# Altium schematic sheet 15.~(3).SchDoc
size 401 x 287 mm
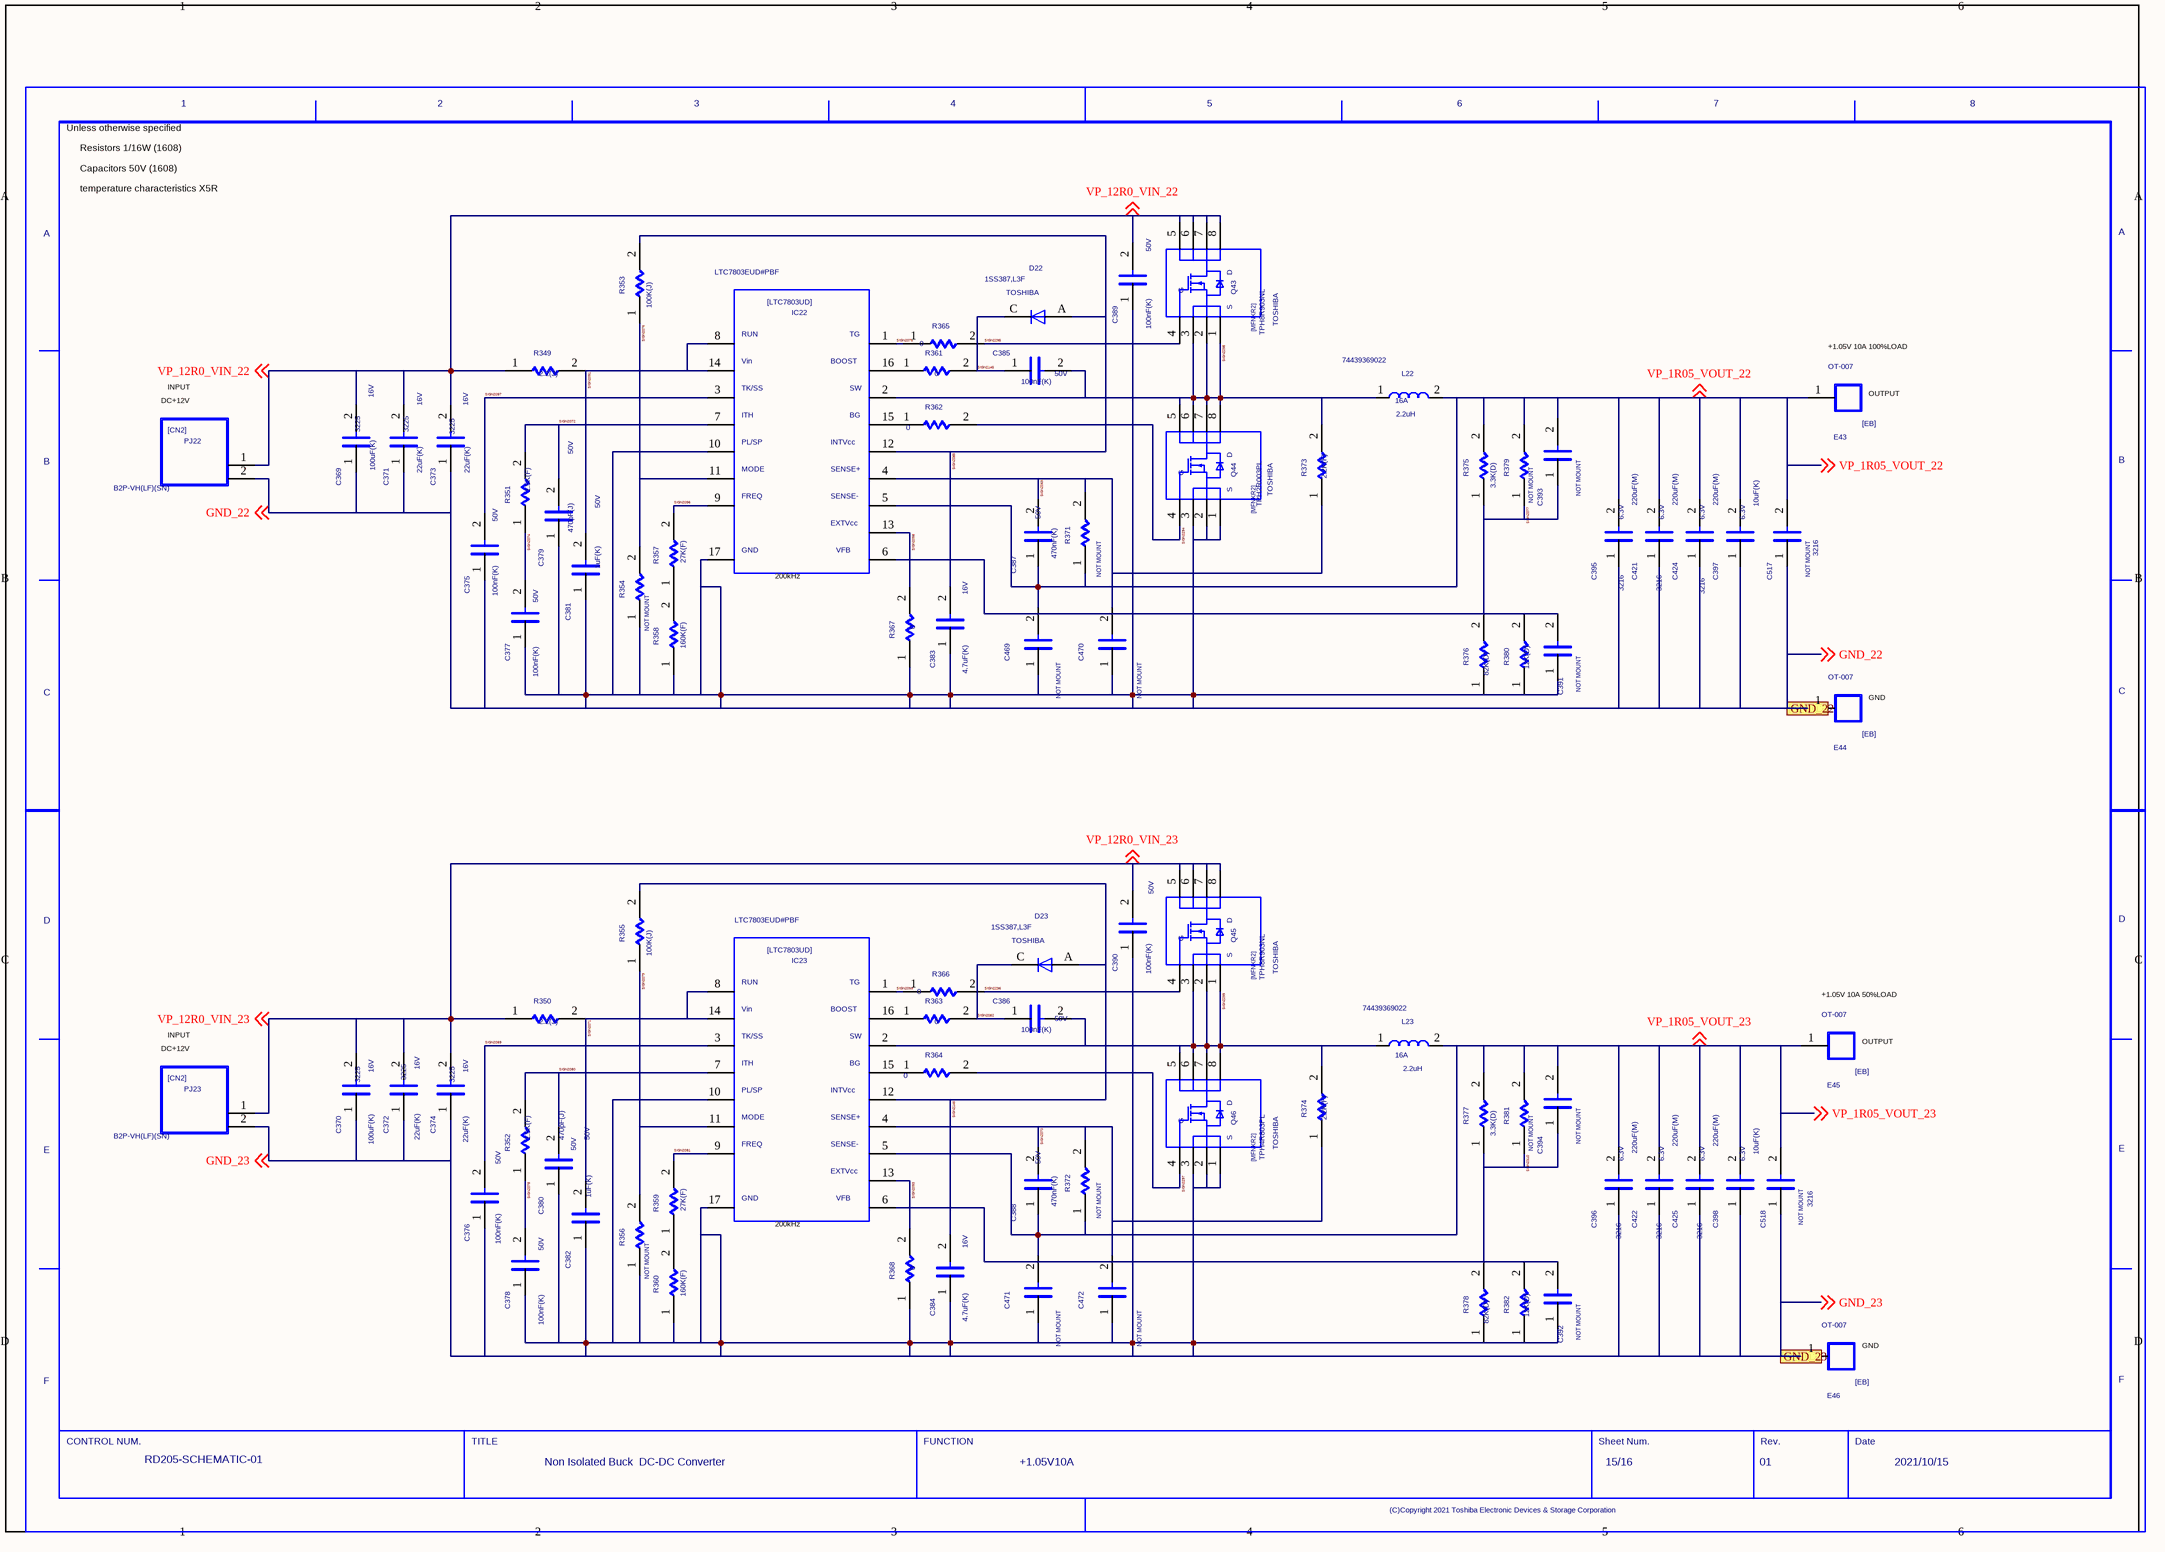
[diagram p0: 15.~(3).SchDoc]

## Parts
C369  SIZECODESMD: 3225  VAL2: 16V  VAL1: 100uF(K)  (hidden comment: C)
C370  SIZECODESMD: 3225  VAL2: 16V  VAL1: 100uF(K)  (hidden comment: C)
C371  SIZECODESMD: 3225  VAL2: 16V  VAL1: 22uF(K)  (hidden comment: C)
C372  SIZECODESMD: 3225  VAL2: 16V  VAL1: 22uF(K)  (hidden comment: C)
C373  SIZECODESMD: 3225  VAL2: 16V  VAL1: 22uF(K)  (hidden comment: C)
C374  SIZECODESMD: 3225  VAL2: 16V  VAL1: 22uF(K)  (hidden comment: C)
C375  VAL2: 50V  VAL1: 100nF(K)  (hidden comment: C)
C376  VAL2: 50V  VAL1: 100nF(K)  (hidden comment: C)
C377  VAL2: 50V  VAL1: 100nF(K)  (hidden comment: C)
C378  VAL2: 50V  VAL1: 100nF(K)  (hidden comment: C)
C379  VAL2: 50V  VAL1: 470pF(J)  (hidden comment: C)
C380  VAL2: 50V  VAL1: 470pF(J)  (hidden comment: C)
C381  VAL2: 50V  VAL1: 1uF(K)  (hidden comment: C)
C382  VAL2: 50V  VAL1: 1uF(K)  (hidden comment: C)
C383  VAL2: 16V  VAL1: 4.7uF(K)  (hidden comment: C)
C384  VAL2: 16V  VAL1: 4.7uF(K)  (hidden comment: C)
C385  VAL2: 50V  VAL1: 100nF(K)  (hidden comment: C)
C386  VAL2: 50V  VAL1: 100nF(K)  (hidden comment: C)
C387  VAL2: 50V  VAL1: 470nF(K)  (hidden comment: C)
C388  VAL2: 50V  VAL1: 470nF(K)  (hidden comment: C)
C389  VAL2: 50V  VAL1: 100nF(K)  (hidden comment: C)
C390  VAL2: 50V  VAL1: 100nF(K)  (hidden comment: C)
C391  NOTMOUNT: NOT MOUNT  (hidden comment: C)
C392  NOTMOUNT: NOT MOUNT  (hidden comment: C)
C393  NOTMOUNT: NOT MOUNT  (hidden comment: C)
C394  NOTMOUNT: NOT MOUNT  (hidden comment: C)
C395  SIZECODESMD: 3216  VAL2: 6.3V  VAL1: 220uF(M)  (hidden comment: C)
C396  SIZECODESMD: 3216  VAL2: 6.3V  VAL1: 220uF(M)  (hidden comment: C)
C397  VAL2: 6.3V  VAL1: 10uF(K)  (hidden comment: C)
C398  VAL2: 6.3V  VAL1: 10uF(K)  (hidden comment: C)
C421  SIZECODESMD: 3216  VAL2: 6.3V  VAL1: 220uF(M)  (hidden comment: C)
C422  SIZECODESMD: 3216  VAL2: 6.3V  VAL1: 220uF(M)  (hidden comment: C)
C424  SIZECODESMD: 3216  VAL2: 6.3V  VAL1: 220uF(M)  (hidden comment: C)
C425  SIZECODESMD: 3216  VAL2: 6.3V  VAL1: 220uF(M)  (hidden comment: C)
C469  NOTMOUNT: NOT MOUNT  (hidden comment: C)
C470  NOTMOUNT: NOT MOUNT  (hidden comment: C)
C471  NOTMOUNT: NOT MOUNT  (hidden comment: C)
C472  NOTMOUNT: NOT MOUNT  (hidden comment: C)
C517  NOTMOUNT: NOT MOUNT  SIZECODESMD: 3216  (hidden comment: C)
C518  NOTMOUNT: NOT MOUNT  SIZECODESMD: 3216  (hidden comment: C)
D22  USERCOMPTEXT3: TOSHIBA  VAL3: 1SS387,L3F  (hidden comment: D)
D23  USERCOMPTEXT3: TOSHIBA  VAL3: 1SS387,L3F  (hidden comment: D)
E43  VAL3: OT-007  (hidden comment: EB)
E44  VAL3: OT-007  (hidden comment: EB)
E45  VAL3: OT-007  (hidden comment: EB)
E46  VAL3: OT-007  (hidden comment: EB)
IC22  VAL3: LTC7803EUD#PBF  (hidden comment: LTC7803UD)
IC23  VAL3: LTC7803EUD#PBF  (hidden comment: LTC7803UD)
L22  VAL3: 74439369022  VAL2: 16A  VAL1: 2.2uH  (hidden comment: L)
L23  VAL3: 74439369022  VAL2: 16A  VAL1: 2.2uH  (hidden comment: L)
PJ22  VAL3: B2P-VH(LF)(SN)  (hidden comment: CN2)
PJ23  VAL3: B2P-VH(LF)(SN)  (hidden comment: CN2)
Q43  USERCOMPTEXT3: TOSHIBA  VAL3: TPH8R903NL  (hidden comment: MFNKR2)
Q44  USERCOMPTEXT3: TOSHIBA  VAL3: TPH2R003PL  (hidden comment: MFNKR2)
Q45  USERCOMPTEXT3: TOSHIBA  VAL3: TPH8R903NL  (hidden comment: MFNKR2)
Q46  USERCOMPTEXT3: TOSHIBA  VAL3: TPH4R803PL  (hidden comment: MFNKR2)
R349  VAL1: 2.2(J)  (hidden comment: R)
R350  VAL1: 2.2(J)  (hidden comment: R)
R351  VAL1: 1.5K(F)  (hidden comment: R)
R352  VAL1: 1.5K(F)  (hidden comment: R)
R353  VAL1: 100K(J)  (hidden comment: R)
R354  NOTMOUNT: NOT MOUNT  (hidden comment: R)
R355  VAL1: 100K(J)  (hidden comment: R)
R356  NOTMOUNT: NOT MOUNT  (hidden comment: R)
R357  VAL1: 27K(F)  (hidden comment: R)
R358  VAL1: 160K(F)  (hidden comment: R)
R359  VAL1: 27K(F)  (hidden comment: R)
R360  VAL1: 160K(F)  (hidden comment: R)
R361  VAL1: 0  (hidden comment: R)
R362  VAL1: 0  (hidden comment: R)
R363  VAL1: 0  (hidden comment: R)
R364  VAL1: 0  (hidden comment: R)
R365  VAL1: 0  (hidden comment: R)
R366  VAL1: 0  (hidden comment: R)
R367  VAL1: 0  (hidden comment: R)
R368  VAL1: 0  (hidden comment: R)
R371  NOTMOUNT: NOT MOUNT  (hidden comment: R)
R372  NOTMOUNT: NOT MOUNT  (hidden comment: R)
R373  VAL1: 2.2K(F)  (hidden comment: R)
R374  VAL1: 2.2K(F)  (hidden comment: R)
R375  VAL1: 3.3K(D)  (hidden comment: R)
R376  VAL1: 82K(D)  (hidden comment: R)
R377  VAL1: 3.3K(D)  (hidden comment: R)
R378  VAL1: 82K(D)  (hidden comment: R)
R379  NOTMOUNT: NOT MOUNT  (hidden comment: R)
R380  VAL1: 12K(D)  (hidden comment: R)
R381  NOTMOUNT: NOT MOUNT  (hidden comment: R)
R382  VAL1: 12K(D)  (hidden comment: R)
U?  DATE: 2021/10/15  SHEETNUMBER: 15/16  TITLE: Non Isolated Buck / DC-DC Converter  REVISION: 01  DRAWINGNUMBER: RD205-SCHEMATIC-01  FUNCTION: +1.05V10A  (hidden comment: WAKU_DEF100)

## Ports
GND_22, GND_23

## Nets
GND_22: C369.1 C371.1 C373.1 C375.1 C377.1 C379.1 C381.1 C383.1 C389.1 C391.1 C395.1 C397.1 C421.1 C424.1 C469.1 C470.1 C517.1 E44.1 IC22.10 IC22.17 PJ22.2 Q44.1 Q44.2 Q44.3 R354.1 R358.1 R367.1 R376.1 R380.1 ; off-sheet GND_22, port GND_22
GND_23: C370.1 C372.1 C374.1 C376.1 C378.1 C380.1 C382.1 C384.1 C390.1 C392.1 C396.1 C398.1 C422.1 C425.1 C471.1 C472.1 C518.1 E46.1 IC23.10 IC23.17 PJ23.2 Q46.1 Q46.2 Q46.3 R356.1 R360.1 R368.1 R378.1 R382.1 ; off-sheet GND_23, port GND_23
SIGN2069: C387.2 C470.2 IC22.4 R371.2 R373.1
SIGN2071: C382.2 IC23.8 IC23.14 R350.2
SIGN2072: C379.2 IC22.7 R351.2
SIGN2073: C388.2 C472.2 IC23.4 R372.2 R374.1
SIGN2074: C377.2 R351.1
SIGN2075: IC22.1 R365.1
SIGN2076: IC22.11 R353.1 R354.2
SIGN2077: C391.2 C393.1 IC22.6 R375.1 R376.2 R379.1 R380.2
SIGN2078: C378.2 R352.1
SIGN2079: IC23.11 R355.1 R356.2
SIGN2080: C380.2 IC23.7 R352.2
SIGN2081: IC23.9 R359.2
SIGN2082: C386.1 D23.C R363.2
SIGN2085: C383.2 D22.A IC22.12 R353.2
SIGN2089: C376.2 IC23.3
SIGN2091: C381.2 IC22.8 IC22.14 R349.2
SIGN2093: IC23.13 R368.2
SIGN2096: IC22.9 R357.2
SIGN2097: C375.2 IC22.3
SIGN2098: IC22.13 R367.2
SIGN2099: IC23.1 R366.1
SIGN2145: C385.1 D22.C R361.2
SIGN2146: C384.2 D23.A IC23.12 R355.2
SIGN2294: Q44.4 R362.2
SIGN2295: Q43.4 R365.2
SIGN2296: Q45.4 R366.2
SIGN2297: Q46.4 R364.2
SIGN2298: C385.2 IC22.2 L22.1 Q43.1 Q43.2 Q43.3 Q44.5 Q44.6 Q44.7 Q44.8 R373.2
SIGN2299: C386.2 IC23.2 L23.1 Q45.1 Q45.2 Q45.3 Q46.5 Q46.6 Q46.7 Q46.8 R374.2
SIGN2310: C392.2 C394.1 IC23.6 R377.1 R378.2 R381.1 R382.2
VP_1R05_VOUT_22: C387.1 C393.2 C395.2 C397.2 C421.2 C424.2 C469.2 C517.2 E43.1 IC22.5 L22.2 R371.1 R375.2 R379.2 ; off-sheet VP_1R05_VOUT_22
VP_1R05_VOUT_23: C388.1 C394.2 C396.2 C398.2 C422.2 C425.2 C471.2 C518.2 E45.1 IC23.5 L23.2 R372.1 R377.2 R381.2 ; off-sheet VP_1R05_VOUT_23
VP_12R0_VIN_22: C369.2 C371.2 C373.2 C389.2 PJ22.1 Q43.5 Q43.6 Q43.7 Q43.8 R349.1 ; off-sheet VP_12R0_VIN_22
VP_12R0_VIN_23: C370.2 C372.2 C374.2 C390.2 PJ23.1 Q45.5 Q45.6 Q45.7 Q45.8 R350.1 ; off-sheet VP_12R0_VIN_23
NetIC22_15: IC22.15 R362.1
NetIC22_16: IC22.16 R361.1
NetIC23_15: IC23.15 R364.1
NetIC23_16: IC23.16 R363.1
NetR357_1: R357.1 R358.2
NetR359_1: R359.1 R360.2

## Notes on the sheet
- Unless otherwise specified
- Resistors 1/16W (1608)
- Capacitors 50V (1608)
- temperature characteristics X5R
- DC+12V
- INPUT
- (near E43) +1.05V 10A 100%LOAD
- (near E43) OUTPUT
- (near IC22) 200kHz
- (near E44) GND
- (near E45) +1.05V 10A 50%LOAD
- (near E45) OUTPUT
- (near IC23) 200kHz
- (near E46) GND

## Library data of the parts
C369 C370 = C: SQ_PART_MODEL: CON_100n; FNPARTSNAMEG: CHIP CERAMIC CAPACITOR (3225); USEINPARTSLIST: YES; OriginalSymbolOrigin: (2540,7620); MFSOLDERINGPROP: .; TEMPCHARACTERI2: B; MFFORMINGDIVP: KC; OUMECLASSIFICATION: セラミックコンデンサ; MFMOUNTSYMBOLP: 90; CDMASTERCADCELG: DC903A; PCODE: P03276001115; FNCLASSCODEG: P03-03; MAXGCOUNT: 1; RATEDVOLTAGE: 250; COMPONENTNAME: G36030160049; OUMEMAKER: KYC 京セラ; MFPACKAGEMETHOP: S; NOMINALCAPACITA: 100n; OUMEMAKERKATAMEI: CF32W5R104K250AT; CAPACITANCETOLE: K
C371-C374 = C: SQ_PART_MODEL: CON_22u; FNPARTSNAMEG: CHIP CERAMIC CAPACITOR (3225); USEINPARTSLIST: YES; OriginalSymbolOrigin: (2540,7620); MFSOLDERINGPROP: .; TEMPCHARACTERI2: B; MFFORMINGDIVP: KC; OUMECLASSIFICATION: セラミックコンデンサ; MFMOUNTSYMBOLP: 80; CDMASTERCADCELG: DC903A; PCODE: P03043035626; FNCLASSCODEG: P03-03; MAXGCOUNT: 1; RATEDVOLTAGE: 6.3; COMPONENTNAME: G36030119054; OUMEMAKER: TYD 太陽誘電; MFPACKAGEMETHOP: S; NOMINALCAPACITA: 22u; OUMEMAKERKATAMEI: JMK325BJ226KM-T; CAPACITANCETOLE: K
C375-C378 C385 C386 C389 C390 = C: SQ_PART_MODEL: CON_100n; FNPARTSNAMEG: CHIP CERAMIC CAPACITOR (1608); USEINPARTSLIST: YES; OriginalSymbolOrigin: (2540,7620); MFSOLDERINGPROP: .; TEMPCHARACTERI2: B; MFFORMINGDIVP: KC; OUMECLASSIFICATION: セラミックコンデンサ; SIZECODESMD: 1608; MFMOUNTSYMBOLP: 80; CDMASTERCADCELG: C8100E; PCODE: P03B000000E4; FNCLASSCODEG: P03-03; MAXGCOUNT: 1; RATEDVOLTAGE: 16; COMPONENTNAME: GDM030000598; OUMEMAKER: MRT 村田製作所; MFPACKAGEMETHOP: S; NOMINALCAPACITA: 100n; OUMEMAKERKATAMEI: GRM188B11C104KA01C; CAPACITANCETOLE: K
C379 C380 = C: SQ_PART_MODEL: CON_470p; FNPARTSNAMEG: CHIP CERAMIC CAPACITOR (1608); USEINPARTSLIST: YES; OriginalSymbolOrigin: (2540,7620); TOLERANCE: J; ASIMVALUE: 470P; CDMASTERCADCELG: C8100E; MFSOLDERINGPROP: .; TEMPCHARACTERI2: CH; MFFORMINGDIVP: KC; OUMECLASSIFICATION: セラミックコンデンサ; SIZECODESMD: 1608; MFMOUNTSYMBOLP: 80; PCODE: P03039329128; FNCLASSCODEG: P03-03; MAXGCOUNT: 1; RATEDVOLTAGE: 50; COMPONENTNAME: G36030011372; OUMEMAKER: KYC 京セラ; MFPACKAGEMETHOP: S; OUMEMAKERKATAMEI: CM105CH471J50AT
C381 C382 = C: SQ_PART_MODEL: CON_1u; FNPARTSNAMEG: CHIP CERAMIC CAPACITOR (1608); USEINPARTSLIST: YES; OriginalSymbolOrigin: (2540,7620); MFSOLDERINGPROP: .; TEMPCHARACTERI2: B; MFFORMINGDIVP: KC; OUMECLASSIFICATION: セラミックコンデンサ; SIZECODESMD: 1608; MFMOUNTSYMBOLP: 80; CDMASTERCADCELG: C8100E; PCODE: P03039ACE122; FNCLASSCODEG: P03-03; MAXGCOUNT: 1; RATEDVOLTAGE: 6.3; COMPONENTNAME: G36030104159; OUMEMAKER: KYC 京セラ; MFPACKAGEMETHOP: S; NOMINALCAPACITA: 1u; OUMEMAKERKATAMEI: CM105B105K06ATN; CAPACITANCETOLE: K
C383 C384 = C: SQ_PART_MODEL: CON_4.7u; FNPARTSNAMEG: CHIP CERAMIC CAPACITOR (1608); USEINPARTSLIST: YES; OriginalSymbolOrigin: (2540,7620); MFSOLDERINGPROP: .; TEMPCHARACTERI2: B; MFFORMINGDIVP: KC; OUMECLASSIFICATION: セラミックコンデンサ; SIZECODESMD: 1608; MFMOUNTSYMBOLP: 80; CDMASTERCADCELG: C8100E; PCODE: P03B000000MS; FNCLASSCODEG: P03-03; MAXGCOUNT: 1; RATEDVOLTAGE: 4; COMPONENTNAME: GDM030000053; OUMEMAKER: KYC 京セラ; MFPACKAGEMETHOP: S; NOMINALCAPACITA: 4.7u; OUMEMAKERKATAMEI: CM105B475M04AT; CAPACITANCETOLE: M
C387 C388 = C: SQ_PART_MODEL: CON_470n; FNPARTSNAMEG: CHIP CERAMIC CAPACITOR (1608); USEINPARTSLIST: YES; OriginalSymbolOrigin: (2540,7620); MFSOLDERINGPROP: .; TEMPCHARACTERI2: B; MFFORMINGDIVP: KC; OUMECLASSIFICATION: セラミックコンデンサ; SIZECODESMD: 1608; MFMOUNTSYMBOLP: 80; CDMASTERCADCELG: C8100E; PCODE: P03039ABG127; FNCLASSCODEG: P03-03; MAXGCOUNT: 1; RATEDVOLTAGE: 10; COMPONENTNAME: GDM030001129; OUMEMAKER: KYC 京セラ; MFPACKAGEMETHOP: S; NOMINALCAPACITA: 470n; OUMEMAKERKATAMEI: CM105B474K10AT; CAPACITANCETOLE: K
C391-C394 = C: SQ_PART_MODEL: CON_100p; FNPARTSNAMEG: CHIP CERAMIC CAPACITOR (1608); USEINPARTSLIST: YES; OriginalSymbolOrigin: (2540,7620); TOLERANCE: J; ASIMVALUE: 100P; MFSOLDERINGPROP: .; TEMPCHARACTERI2: CH; MFFORMINGDIVP: KC; OUMECLASSIFICATION: セラミックコンデンサ; SIZECODESMD: 1608; MFMOUNTSYMBOLP: 80; CDMASTERCADCELG: C8100E; PCODE: P03039177125; FNCLASSCODEG: P03-03; MAXGCOUNT: 1; RATEDVOLTAGE: 50; COMPONENTNAME: G36030011365; OUMEMAKER: KYC 京セラ; MFPACKAGEMETHOP: S; OUMEMAKERKATAMEI: CM105CH101J50AT; VAL2: 50V; VAL1: 100pF(J)
C395 C396 C421 C422 C424 C425 = C: SQ_PART_MODEL: CON_22u; FNPARTSNAMEG: CHIP CERAMIC CAPACITOR (3216); USEINPARTSLIST: YES; OriginalSymbolOrigin: (2540,7620); MFSOLDERINGPROP: .; TEMPCHARACTERI2: B; MFFORMINGDIVP: KC; OUMECLASSIFICATION: セラミックコンデンサ; MFMOUNTSYMBOLP: 80; CDMASTERCADCELG: DC901A; PCODE: P03B0000004V; FNCLASSCODEG: P03-03; MAXGCOUNT: 1; RATEDVOLTAGE: 6.3; COMPONENTNAME: GDM030000020; OUMEMAKER: KYC 京セラ; MFPACKAGEMETHOP: S; NOMINALCAPACITA: 22u; OUMEMAKERKATAMEI: CM316B226M06AT; CAPACITANCETOLE: M
C397 C398 = C: SQ_PART_MODEL: CON_1u; FNPARTSNAMEG: CHIP CERAMIC CAPACITOR (1608); PARTCOMMENT: 代表セル<KC0008> がフットプリントに登録されていません。; USEINPARTSLIST: YES; OriginalSymbolOrigin: (2540,7620); MFSOLDERINGPROP: .; TEMPCHARACTERI2: B; MFFORMINGDIVP: KC; OUMECLASSIFICATION: セラミックコンデンサ; SIZECODESMD: 1608; MFMOUNTSYMBOLP: 80; CDMASTERCADCELG: KC0008; PCODE: P03B000000ZQ; FNCLASSCODEG: P03-03; MAXGCOUNT: 1; RATEDVOLTAGE: 6.3; COMPONENTNAME: GDM030000202; OUMEMAKER: MRT 村田製作所; MFPACKAGEMETHOP: S; NOMINALCAPACITA: 1u; OUMEMAKERKATAMEI: GRM185B10J105KE21D; CAPACITANCETOLE: K
C469-C472 = C: SQ_PART_MODEL: CON_220n; FNPARTSNAMEG: CHIP CERAMIC CAPACITOR (1608); PARTCOMMENT: 代表セル<KC0008> がフットプリントに登録されていません。; USEINPARTSLIST: YES; OriginalSymbolOrigin: (2540,7620); MFSOLDERINGPROP: .; TEMPCHARACTERI2: B; MFFORMINGDIVP: KC; OUMECLASSIFICATION: セラミックコンデンサ; SIZECODESMD: 1608; MFMOUNTSYMBOLP: 80; CDMASTERCADCELG: KC0008; PCODE: P03B000001L3; FNCLASSCODEG: P03-03; MAXGCOUNT: 1; RATEDVOLTAGE: 16; COMPONENTNAME: GDM030001129; OUMEMAKER: MRT 村田製作所; MFPACKAGEMETHOP: S; NOMINALCAPACITA: 220n; OUMEMAKERKATAMEI: GRM188B11C224KA01D; VAL2: 16V; VAL1: 220nF(K); CAPACITANCETOLE: K
C517 C518 = C: SQ_PART_MODEL: CON_22u; FNPARTSNAMEG: CHIP CERAMIC CAPACITOR (3216); USEINPARTSLIST: YES; OriginalSymbolOrigin: (2540,7620); MFSOLDERINGPROP: .; TEMPCHARACTERI2: B; MFFORMINGDIVP: KC; OUMECLASSIFICATION: セラミックコンデンサ; MFMOUNTSYMBOLP: 80; CDMASTERCADCELG: DC901A; PCODE: P03B0000004V; FNCLASSCODEG: P03-03; MAXGCOUNT: 1; RATEDVOLTAGE: 6.3; COMPONENTNAME: GDM030000020; OUMEMAKER: KYC 京セラ; MFPACKAGEMETHOP: S; NOMINALCAPACITA: 22u; OUMEMAKERKATAMEI: CM316B226M06AT; VAL2: 6.3V; VAL1: 22uF(M); CAPACITANCETOLE: M
D22 D23 = D: FNPARTSNAMEG: DIODE; USEINPARTSLIST: YES; PARTNAME: GDM420000143; SAVEAREA0: -565,-171,12979,8058; SAVECOUNT: 1; TIME: 14:49:55; UPDATEUSER: 19870035; UPDATETIME: 14:20:16; OriginalSymbolOrigin: (5080,5080); FORWARDVOLTAGEM: 0; MAXREVERSEVOLTA: 80; COMPONENTNAME: GDM420000143_package; MFSOLDERINGPROP: .; OUMEMAKER: TSB 東芝（ＹＰＳＳ）; QUADMODEL: dummymodel; MFPACKAGEMETHOP: S; MFFORMINGDIVP: MM; MOUNTINGFORMSMD: SMD; OUMECLASSIFICATION: 小信号ダイオード; OUMEMAKERKATAMEI: 1SS387(TPH3,F); CDMASTERCADCELG: D8101D; PCODE: P42B0000008E; FNCLASSCODEG: P42-01
E43-E46 = EB: FNPARTSNAMEG: TERMINAL; USEINPARTSLIST: YES; PARTNAME: 5P9L1232P001; OUMEPARTTYPE: TB; OriginalSymbolOrigin: (2540,12700); COMPONENTNAME: 5P9L1232P001_package; MAXGCOUNT: 1; MFSOLDERINGPROP: .; OUMEMAKER: オサダ; QUADMODEL: dummymodel; MFPACKAGEMETHOP: I; MFFORMINGDIVP: OD; OUMECLASSIFICATION: 端子台、端子板; CDMASTERCADCELG: DE0009; KIND: PBS; PCODE: P29045001117; TERMINALSTYLE: SC; FNCLASSCODEG: P29-01
IC22 IC23 = LTC7803UD: USEINPARTSLIST: YES; SAVECOUNT: 29; SAVEAREA0: -53177,0,89020,58420; TIME: 16:14:14; UPDATEUSER: q91866sr; UPDATETIME: 13:15:36; OriginalSymbolOrigin: (5080,55880); MAXGCOUNT: 1; COMPONENTNAME: LTC7803UD_LTC7803UD; OUMEMAKER: ANALOG DEVICES
L22 L23 = L: USEINPARTSLIST: YES; PARTNAME: 74439369033; OriginalSymbolOrigin: (2540,5080); MAXGCOUNT: 1; COMPONENTNAME: L_L; OUMEMAKER: WURTH
PJ22 PJ23 = CN2: FNPARTSNAMEG: 3.96PITCH NYLON CONNECTOR; USEINPARTSLIST: YES; PARTNAME: G36220114012; OUMEPARTTYPE: CN; OriginalSymbolOrigin: (2540,15240); MAXGCOUNT: 1; RATEDCURRENT: 7; COMPONENTNAME: G36220114012_package; MFSOLDERINGPROP: .; OUMEMAKER: JST 日本圧着端子製造; NUMBEROFCONTACT: 2; QUADMODEL: dummymodel; MFPACKAGEMETHOP: I; MFFORMINGDIVP: CU; CONTACTPITCH: 3.96m; OUMEMAKERKATAMEI: B2P-VH; CDMASTERCADCELG: DPJ514; PCODE: P22346001114; TERMINALSTYLE: PW; FNCLASSCODEG: P22-10
Q43-Q46 = MFNKR2: USEINPARTSLIST: YES; PARTNAME: TPH6R003NL; SAVEAREA0: -9199,-39,32138,22820; TIME: 18:57:44; UPDATEUSER: q91866sr; UPDATETIME: 12:36:02; SAVECOUNT: 10; OriginalSymbolOrigin: (5080,20320); MAXGCOUNT: 1; COMPONENTNAME: MFNKR2_MFNKR2
R349 R350 = R: SQ_PART_MODEL: RES_2.2; FNPARTSNAMEG: CHIP RESISTOR (1608); USEINPARTSLIST: YES; OriginalSymbolOrigin: (5080,5080); TOLERANCE: J; ASIMVALUE: 2.2; MAXGCOUNT: 1; COMPONENTNAME: G36010011507; MFSOLDERINGPROP: .; OUMEMAKER: NAE 松下電子部品; MFPACKAGEMETHOP: S; MFFORMINGDIVP: KC; MOUNTINGFORMSMD: SMD; OUMECLASSIFICATION: 表面実装用固定抵抗器; MFMOUNTSYMBOLP: 80; POWERRATING: 63m; OUMEMAKERKATAMEI: ERJ3GEYJ2R2V; NUMBEROFELEMENT: 0; VAL2: 62.5mW; CDMASTERCADCELG: DR802R; PCODE: P01042157622; FNCLASSCODEG: P01-08
R351 R352 = R: SQ_PART_MODEL: RES_1.5K; FNPARTSNAMEG: CHIP RESISTOR (1608); USEINPARTSLIST: YES; OriginalSymbolOrigin: (5080,5080); TOLERANCE: F; ASIMVALUE: 1.5K; MAXGCOUNT: 1; COMPONENTNAME: G36010027232; MFSOLDERINGPROP: .; OUMEMAKER: HDK 北陸電気工業; MFPACKAGEMETHOP: S; MFFORMINGDIVP: KC; MOUNTINGFORMSMD: SMD; OUMECLASSIFICATION: 表面実装用固定抵抗器; MFMOUNTSYMBOLP: 80; POWERRATING: 63m; OUMEMAKERKATAMEI: CR1/16 152FV; NUMBEROFELEMENT: 0; VAL2: 62.5mW; CDMASTERCADCELG: DR802R; PCODE: P01042512223; FNCLASSCODEG: P01-08
R353 R355 = R: SQ_PART_MODEL: RES_100K; FNPARTSNAMEG: CHIP RESISTOR (1608); USEINPARTSLIST: YES; OriginalSymbolOrigin: (5080,5080); TOLERANCE: F; ASIMVALUE: 100K; MFSOLDERINGPROP: .; MFPACKAGEMETHOP: S; MFFORMINGDIVP: KC; MOUNTINGFORMSMD: SMD; MFMOUNTSYMBOLP: 80; NUMBEROFELEMENT: 0; PCODE: P01042045226; MAXGCOUNT: 1; COMPONENTNAME: G36010011057; OUMEMAKER: HDK 北陸電気工業; OUMECLASSIFICATION: 表面実装用固定抵抗器; POWERRATING: 63m; OUMEMAKERKATAMEI: CR1/16 104FV; VAL2: 62.5mW; CDMASTERCADCELG: DR802R; FNCLASSCODEG: P01-08
R354 R356 = R: SQ_PART_MODEL: RES_10; FNPARTSNAMEG: CHIP RESISTOR (1608); USEINPARTSLIST: YES; OriginalSymbolOrigin: (5080,5080); TOLERANCE: F; ASIMVALUE: 10; MFSOLDERINGPROP: .; MFPACKAGEMETHOP: S; MFFORMINGDIVP: KC; MOUNTINGFORMSMD: SMD; MFMOUNTSYMBOLP: 80; NUMBEROFELEMENT: 0; PCODE: P01042036620; MAXGCOUNT: 1; COMPONENTNAME: G36010104063; OUMEMAKER: NAE 松下電子部品; OUMECLASSIFICATION: 表面実装用固定抵抗器; POWERRATING: 63m; OUMEMAKERKATAMEI: ERJ3GEYF100V; VAL2: 62.5mW; VAL1: 10(F); CDMASTERCADCELG: DR802R; FNCLASSCODEG: P01-08
R357 R359 = R: SQ_PART_MODEL: RES_27K; FNPARTSNAMEG: CHIP RESISTOR (1608); USEINPARTSLIST: YES; OriginalSymbolOrigin: (5080,5080); MAXGCOUNT: 1; TOLERANCE: F; COMPONENTNAME: G36010104117; MFSOLDERINGPROP: .; OUMEMAKER: NAE 松下電子部品; MFPACKAGEMETHOP: S; MFFORMINGDIVP: KC; MOUNTINGFORMSMD: SMD; OUMECLASSIFICATION: 表面実装用固定抵抗器; ASIMVALUE: 27K; MFMOUNTSYMBOLP: 80; POWERRATING: 63m; OUMEMAKERKATAMEI: ERJ3GEYF273V; NUMBEROFELEMENT: 0; VAL2: 62.5mW; CDMASTERCADCELG: DR802R; PCODE: P01042508622; FNCLASSCODEG: P01-08
R358 R360 = R: SQ_PART_MODEL: RES_160K; FNPARTSNAMEG: CHIP RESISTOR (1608); USEINPARTSLIST: YES; OriginalSymbolOrigin: (5080,5080); MAXGCOUNT: 1; COMPONENTNAME: G36010104223; MFSOLDERINGPROP: .; OUMEMAKER: HDK 北陸電気工業; MFPACKAGEMETHOP: S; MFFORMINGDIVP: KC; MOUNTINGFORMSMD: SMD; OUMECLASSIFICATION: 表面実装用固定抵抗器; RESISTANCETOLER: F; MFMOUNTSYMBOLP: 80; POWERRATING: 63m; OUMEMAKERKATAMEI: CR1/16 164FV; NOMINALRESISTAN: 160K; NUMBEROFELEMENT: 0; VAL2: 62.5mW; CDMASTERCADCELG: DR802R; PCODE: P01042125225; FNCLASSCODEG: P01-08
R361 R363 R367 R368 = R: SQ_PART_MODEL: RES_10; FNPARTSNAMEG: CHIP RESISTOR (1608); USEINPARTSLIST: YES; OriginalSymbolOrigin: (5080,5080); TOLERANCE: F; ASIMVALUE: 10; MFSOLDERINGPROP: .; MFPACKAGEMETHOP: S; MFFORMINGDIVP: KC; MOUNTINGFORMSMD: SMD; MFMOUNTSYMBOLP: 80; PCODE: P01042036620; MAXGCOUNT: 1; COMPONENTNAME: G36010104063; OUMEMAKER: NAE 松下電子部品; OUMECLASSIFICATION: 表面実装用固定抵抗器; POWERRATING: 63m; OUMEMAKERKATAMEI: ERJ3GEYF100V; VAL2: 62.5mW; CDMASTERCADCELG: DR802R; FNCLASSCODEG: P01-08
R362 R364-R366 = R: SQ_PART_MODEL: RES_10; FNPARTSNAMEG: CHIP RESISTOR (2012); USEINPARTSLIST: YES; OriginalSymbolOrigin: (5080,5080); MAXGCOUNT: 1; TOLERANCE: F; COMPONENTNAME: 5P9L1083P100; MFSOLDERINGPROP: .; OUMEMAKER: 北陸電気工業; MFPACKAGEMETHOP: S; MFFORMINGDIVP: KC; MOUNTINGFORMSMD: SMD; OUMECLASSIFICATION: 表面実装用固定抵抗器; ASIMVALUE: 10; MFMOUNTSYMBOLP: 90; POWERRATING: 100m; OUMEMAKERKATAMEI: CR1/10 100FV Pb(F); VAL2: 125mW; CDMASTERCADCELG: DR910A; PCODE: P01043091222; FNCLASSCODEG: P01-08
R371 R372 = R: SQ_PART_MODEL: RES_68K; FNPARTSNAMEG: CHIP RESISTOR (1608); USEINPARTSLIST: YES; OriginalSymbolOrigin: (5080,5080); TOLERANCE: F; ASIMVALUE: 68K; MAXGCOUNT: 1; COMPONENTNAME: G36010027126; MFSOLDERINGPROP: .; OUMEMAKER: HDK 北陸電気工業; MFPACKAGEMETHOP: S; MFFORMINGDIVP: KC; MOUNTINGFORMSMD: SMD; OUMECLASSIFICATION: 表面実装用固定抵抗器; MFMOUNTSYMBOLP: 80; POWERRATING: 63m; OUMEMAKERKATAMEI: CR1/16 683FV; NUMBEROFELEMENT: 0; VAL2: 62.5mW; VAL1: 68K(F); CDMASTERCADCELG: DR802R; PCODE: P01042456220; FNCLASSCODEG: P01-08
R373 R374 = R: SQ_PART_MODEL: RES_2.2K; FNPARTSNAMEG: CHIP RESISTOR (1608); USEINPARTSLIST: YES; OriginalSymbolOrigin: (5080,5080); PCODE: P01042159428; MAXGCOUNT: 1; COMPONENTNAME: G36010027249; MFSOLDERINGPROP: .; OUMEMAKER: KOA ＫＯＡ; MFPACKAGEMETHOP: S; MFFORMINGDIVP: KC; MOUNTINGFORMSMD: SMD; OUMECLASSIFICATION: 表面実装用固定抵抗器; RESISTANCETOLER: F; MFMOUNTSYMBOLP: 80; POWERRATING: 63m; OUMEMAKERKATAMEI: RK73H1JTD2201F; NOMINALRESISTAN: 2.2K; NUMBEROFELEMENT: 0; VAL2: 62.5mW; CDMASTERCADCELG: DR802R; FNCLASSCODEG: P01-08
R375 R377 = R: SQ_PART_MODEL: RES_3.3K; FNPARTSNAMEG: CHIP RESISTOR (1608); USEINPARTSLIST: YES; OriginalSymbolOrigin: (5080,5080); MAXGCOUNT: 1; COMPONENTNAME: G36010014485; MFSOLDERINGPROP: .; OUMEMAKER: SSM 進工業; MFPACKAGEMETHOP: S; MFFORMINGDIVP: KC; MOUNTINGFORMSMD: SMD; OUMECLASSIFICATION: 表面実装用固定抵抗器; RESISTANCETOLER: D; MFMOUNTSYMBOLP: 80; POWERRATING: 63m; OUMEMAKERKATAMEI: RR0816P-332-D; NOMINALRESISTAN: 3.3K; NUMBEROFELEMENT: 0; VAL2: 62.5mW; CDMASTERCADCELG: DR802R; PCODE: P01042249822; FNCLASSCODEG: P01-08
R376 R378 = R: ICX_PART_MODEL: RES_82K; FNPARTSNAMEG: CHIP RESISTOR (1608); OriginalSymbolOrigin: (5080,5080); FNCLASSCODEG: P01-08; PCODE: P01117075110; CDMASTERCADCELG: DR802R; USEWITHSCHEMA: YES; VAL2: 62.5mW; NUMBEROFELEMENT: 0; NOMINALRESISTAN: 82K; OUMEMAKERKATAMEI: RK73G1JTD823D; POWERRATING: 63m; MFMOUNTSYMBOLP: 80; RESISTANCETOLER: D; FUNCTION: G36010129714; OUMECLASSIFICATION: 表面実装用固定抵抗器; MOUNTINGFORMSMD: SMD; MFFORMINGDIVP: KC; MFPACKAGEMETHOP: S; OUMEMAKER: KOA ＫＯＡ; MFSOLDERINGPROP: .; MAXGCOUNT: 1
R379 R381 = R: SQ_PART_MODEL: RES_3.3K; FNPARTSNAMEG: CHIP RESISTOR (1608); USEINPARTSLIST: YES; OriginalSymbolOrigin: (5080,5080); TOLERANCE: F; ASIMVALUE: 3.3K; MAXGCOUNT: 1; COMPONENTNAME: G36010027027; MFSOLDERINGPROP: .; OUMEMAKER: ROH ロー・; MFPACKAGEMETHOP: S; MFFORMINGDIVP: KC; MOUNTINGFORMSMD: SMD; OUMECLASSIFICATION: 表面実装用固定抵抗器; MFMOUNTSYMBOLP: 80; POWERRATING: 63m; OUMEMAKERKATAMEI: MCR03EZPFX3301; NUMBEROFELEMENT: 0; VAL2: 62.5mW; VAL1: 3.3K(F); CDMASTERCADCELG: DR802R; PCODE: P01042250729; FNCLASSCODEG: P01-08
R380 R382 = R: ICX_PART_MODEL: RES_12K; FNPARTSNAMEG: CHIP RESISTOR (1608); OriginalSymbolOrigin: (5080,5080); FNCLASSCODEG: P01-08; PCODE: P01117055112; CDMASTERCADCELG: DR802R; USEWITHSCHEMA: YES; VAL2: 62.5mW; NUMBEROFELEMENT: 0; NOMINALRESISTAN: 12K; OUMEMAKERKATAMEI: RK73G1JTD123D; POWERRATING: 63m; MFMOUNTSYMBOLP: 80; RESISTANCETOLER: D; FUNCTION: G36010129516; OUMECLASSIFICATION: 表面実装用固定抵抗器; MOUNTINGFORMSMD: SMD; MFFORMINGDIVP: KC; MFPACKAGEMETHOP: S; OUMEMAKER: KOA ＫＯＡ; MFSOLDERINGPROP: .; MAXGCOUNT: 1
U? = WAKU_DEF100: PLOTTIME: HH:MM; SAVEAREA0: 330961,54,387907,31546; TIME: 19:23:07; UPDATEUSER: t5459927; UPDATETIME: 15:33:43; SAVECOUNT: 6; OriginalSymbolOrigin: (10160,284480); DESIGNED: ***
